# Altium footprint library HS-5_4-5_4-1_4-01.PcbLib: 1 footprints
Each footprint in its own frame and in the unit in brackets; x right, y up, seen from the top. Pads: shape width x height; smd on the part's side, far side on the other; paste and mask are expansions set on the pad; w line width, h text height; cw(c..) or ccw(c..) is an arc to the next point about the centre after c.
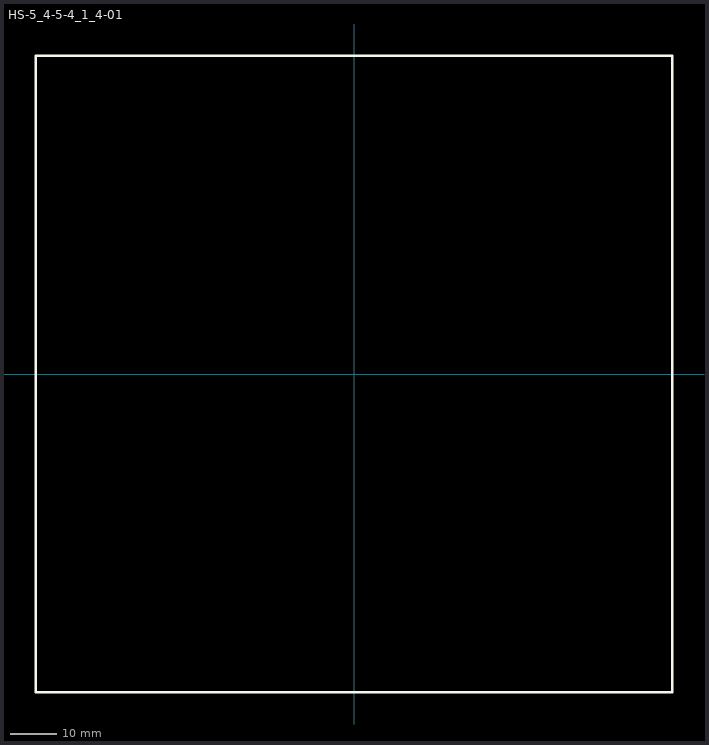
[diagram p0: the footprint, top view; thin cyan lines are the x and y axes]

## HS-5_4-5-4_1_4-01 [mil] "HS5.4-5.4-1.4-01 HEATSINK cUSTOM THERMOELECTRIC"
height 1375
pads (1):
  round 60 on Top Overlay: 0(0,0)
Top Overlay:
  lines w20: -2687.5,-2687.5 2687.5,-2687.5 2687.5,2687.5 -2687.5,2687.5 -2687.5,-2687.5
M5 Assembly Top:
  text ".Designator" at -3.94,-3.94 h40
3D body: height 1375, standoff 0, extent -2680,-2685 2695,2695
